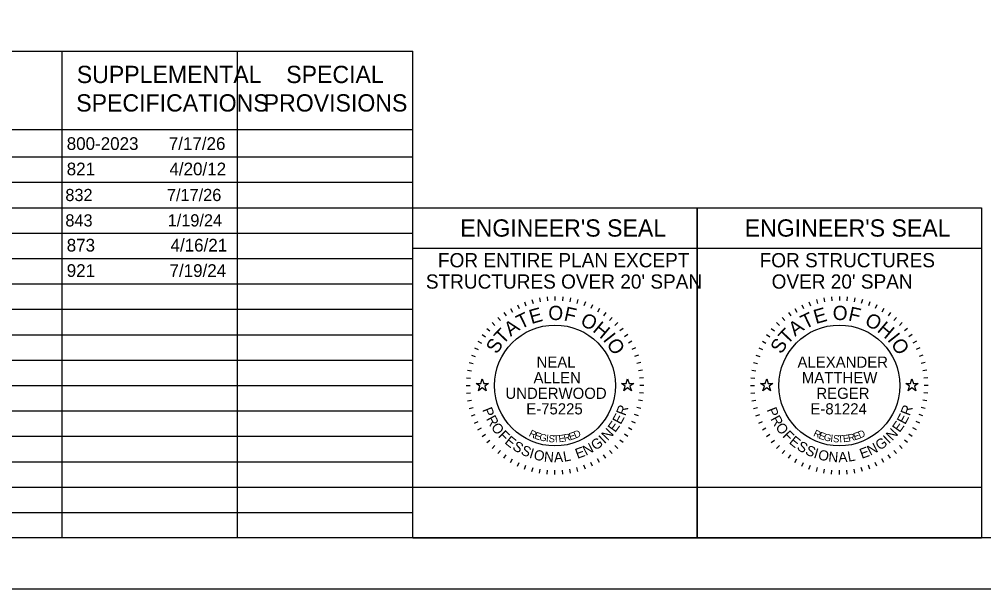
# Model space of a CAD drawing. Extents: x 0 to 34, y 0 to 22.
# Drawn here: x 19.73 to 29.22, y 0 to 5.6 of the extents above; entities that cross this region are included whole.
import ezdxf

# ---------------------------------------------------------------- set-up
doc = ezdxf.new("R2010")
doc.units = 0
for name, color, linetype in [('SH_Border', 7, 'Continuous'), ('SH_Cut_Line', 7, 'Continuous'), ('SH_Data', 7, 'Continuous'), ('SH_Seal', 7, 'Continuous'), ('SH_Text', 7, 'Continuous')]:
    doc.layers.add(name, color=color, linetype=linetype)

msp = doc.modelspace()

# ---------------------------------------------------------------- linework, layer by layer
at = {"layer": 'SH_Border'}
msp.add_lwpolyline([(1.5, 21.5), (33.5, 21.5), (33.5, 0.5), (1.5, 0.5)], close=True, dxfattribs=at)
at = {"layer": 'SH_Cut_Line'}
msp.add_lwpolyline([(0, 0), (34, 0), (34, 22), (0, 22)], close=True, dxfattribs=at)
at = {"layer": 'SH_Data'}
for p, q in [((10.15, 5.2917), (23.6, 5.2917)), ((20.15, 0.5), (20.15, 5.2917)), ((21.875, 0.5), (21.875, 5.2917)), ((23.6, 0.5), (23.6, 5.2917)), ((10.15, 4.5209), (23.6, 4.5209)), ((10.15, 4.25), (23.6, 4.25)), ((10.15, 4), (23.6, 4)), ((10.15, 3.75), (23.6, 3.75)), ((23.6, 0.5), (23.6, 3.75)), ((23.6, 3.75), (26.4, 3.75)), ((23.6, 0.5), (23.6, 3.75)), ((23.6, 3.75), (26.4, 3.75)), ((26.4, 3.75), (26.4, 0.5)), ((26.4, 0.5), (26.4, 3.75)), ((26.4, 0.5), (26.4, 3.75)), ((26.4, 3.75), (29.2, 3.75)), ((26.4, 3.75), (26.4, 0.5)), ((29.2, 3.75), (29.2, 0.5)), ((10.15, 3.5), (23.6, 3.5)), ((23.6, 3.35), (26.4, 3.35)), ((26.4, 3.35), (29.2, 3.35)), ((10.15, 3.25), (23.6, 3.25)), ((10.15, 3), (23.6, 3)), ((10.15, 2.75), (23.6, 2.75)), ((10.15, 2.5), (23.6, 2.5)), ((10.15, 2.25), (23.6, 2.25)), ((10.15, 2), (23.6, 2)), ((10.15, 1.75), (23.6, 1.75)), ((10.15, 1.5), (23.6, 1.5)), ((10.15, 1.25), (23.6, 1.25)), ((10.15, 1), (23.6, 1)), ((10.15, 0.75), (23.6, 0.75)), ((23.6, 0.5), (26.4, 0.5)), ((23.6, 0.5), (26.4, 0.5)), ((26.4, 0.5), (29.2, 0.5)), ((26.4, 0.5), (29.2, 0.5))]:
    msp.add_line(p, q, dxfattribs=at)
for points in [[(23.6, 0.5), (23.6, 1), (26.4, 1), (26.4, 0.5)], [(26.4, 0.5), (26.4, 1), (29.2, 1), (29.2, 0.5)]]:
    msp.add_lwpolyline(points, close=True, dxfattribs=at)
at = {"layer": 'SH_Seal'}
for p, q in [((24.8481, 2.8617), (24.855, 2.8223)), ((24.9237, 2.8717), (24.9272, 2.8318)), ((25, 2.875), (25, 2.835)), ((25.0763, 2.8717), (25.0728, 2.8318)), ((25.1519, 2.8617), (25.145, 2.8223)), ((27.6481, 2.8617), (27.655, 2.8223)), ((27.7237, 2.8717), (27.7272, 2.8318)), ((27.8, 2.875), (27.8, 2.835)), ((27.8763, 2.8717), (27.8728, 2.8318)), ((27.9519, 2.8617), (27.945, 2.8223)), ((24.5625, 2.7578), (24.5825, 2.7231)), ((24.6302, 2.793), (24.6471, 2.7568)), ((24.7007, 2.8222), (24.7144, 2.7846)), ((24.7735, 2.8452), (24.7839, 2.8065)), ((25.2265, 2.8452), (25.2161, 2.8065)), ((25.2993, 2.8222), (25.2856, 2.7846)), ((25.3698, 2.793), (25.3529, 2.7568)), ((25.4375, 2.7578), (25.4175, 2.7231)), ((27.3625, 2.7578), (27.3825, 2.7231)), ((27.4302, 2.793), (27.4471, 2.7568)), ((27.5007, 2.8222), (27.5144, 2.7846)), ((27.5735, 2.8452), (27.5839, 2.8065)), ((28.0265, 2.8452), (28.0161, 2.8065)), ((28.0993, 2.8222), (28.0856, 2.7846)), ((28.1698, 2.793), (28.1529, 2.7568)), ((28.2375, 2.7578), (28.2175, 2.7231)), ((24.4376, 2.6703), (24.4633, 2.6396)), ((24.4981, 2.7168), (24.5211, 2.684)), ((25.5019, 2.7168), (25.4789, 2.684)), ((25.5624, 2.6703), (25.5367, 2.6396)), ((27.2376, 2.6703), (27.2633, 2.6396)), ((27.2981, 2.7168), (27.3211, 2.684)), ((28.3019, 2.7168), (28.2789, 2.684)), ((28.3624, 2.6703), (28.3367, 2.6396)), ((24.3813, 2.6187), (24.4096, 2.5904)), ((25.6187, 2.6187), (25.5904, 2.5904)), ((27.1813, 2.6187), (27.2096, 2.5904)), ((28.4187, 2.6187), (28.3904, 2.5904)), ((24.2832, 2.5019), (24.316, 2.4789)), ((24.3297, 2.5624), (24.3604, 2.5367)), ((25.6703, 2.5624), (25.6396, 2.5367)), ((25.7168, 2.5019), (25.684, 2.4789)), ((27.0832, 2.5019), (27.116, 2.4789)), ((27.1297, 2.5624), (27.1604, 2.5367)), ((28.4703, 2.5624), (28.4396, 2.5367)), ((28.5168, 2.5019), (28.484, 2.4789)), ((24.2422, 2.4375), (24.2769, 2.4175)), ((25.7578, 2.4375), (25.7231, 2.4175)), ((27.0422, 2.4375), (27.0769, 2.4175)), ((28.5578, 2.4375), (28.5231, 2.4175)), ((24.1778, 2.2993), (24.2154, 2.2856)), ((24.207, 2.3698), (24.2432, 2.3529)), ((25.793, 2.3698), (25.7568, 2.3529)), ((25.8222, 2.2993), (25.7846, 2.2856)), ((26.9778, 2.2993), (27.0154, 2.2856)), ((27.007, 2.3698), (27.0432, 2.3529)), ((28.593, 2.3698), (28.5568, 2.3529)), ((28.6222, 2.2993), (28.5846, 2.2856)), ((24.1548, 2.2265), (24.1935, 2.2161)), ((25.8452, 2.2265), (25.8065, 2.2161)), ((26.9548, 2.2265), (26.9935, 2.2161)), ((28.6452, 2.2265), (28.6065, 2.2161)), ((24.1383, 2.1519), (24.1777, 2.145)), ((25.8617, 2.1519), (25.8223, 2.145)), ((26.9383, 2.1519), (26.9777, 2.145)), ((28.6617, 2.1519), (28.6223, 2.145)), ((24.125, 2), (24.165, 2)), ((24.1283, 2.0763), (24.1682, 2.0728)), ((25.8717, 2.0763), (25.8318, 2.0728)), ((25.875, 2), (25.835, 2)), ((26.925, 2), (26.965, 2)), ((26.9283, 2.0763), (26.9682, 2.0728)), ((28.6717, 2.0763), (28.6318, 2.0728)), ((28.675, 2), (28.635, 2)), ((24.1283, 1.9237), (24.1682, 1.9272)), ((25.8717, 1.9237), (25.8318, 1.9272)), ((26.9283, 1.9237), (26.9682, 1.9272)), ((28.6717, 1.9237), (28.6318, 1.9272)), ((24.1383, 1.8481), (24.1777, 1.855)), ((25.8617, 1.8481), (25.8223, 1.855)), ((26.9383, 1.8481), (26.9777, 1.855)), ((28.6617, 1.8481), (28.6223, 1.855)), ((24.1548, 1.7735), (24.1935, 1.7839)), ((24.1778, 1.7007), (24.2154, 1.7144)), ((25.8222, 1.7007), (25.7846, 1.7144)), ((25.8452, 1.7735), (25.8065, 1.7839)), ((26.9548, 1.7735), (26.9935, 1.7839)), ((26.9778, 1.7007), (27.0154, 1.7144)), ((28.6222, 1.7007), (28.5846, 1.7144)), ((28.6452, 1.7735), (28.6065, 1.7839)), ((24.207, 1.6302), (24.2432, 1.6471)), ((25.793, 1.6302), (25.7568, 1.6471)), ((27.007, 1.6302), (27.0432, 1.6471)), ((28.593, 1.6302), (28.5568, 1.6471)), ((24.2422, 1.5625), (24.2769, 1.5825)), ((24.2832, 1.4981), (24.316, 1.5211)), ((25.7168, 1.4981), (25.684, 1.5211)), ((25.7578, 1.5625), (25.7231, 1.5825)), ((27.0422, 1.5625), (27.0769, 1.5825)), ((27.0832, 1.4981), (27.116, 1.5211)), ((28.5168, 1.4981), (28.484, 1.5211)), ((28.5578, 1.5625), (28.5231, 1.5825)), ((24.3297, 1.4376), (24.3604, 1.4633)), ((25.6703, 1.4376), (25.6396, 1.4633)), ((27.1297, 1.4376), (27.1604, 1.4633)), ((28.4703, 1.4376), (28.4396, 1.4633)), ((24.3813, 1.3813), (24.4096, 1.4096)), ((24.4376, 1.3297), (24.4633, 1.3604)), ((25.5624, 1.3297), (25.5367, 1.3604)), ((25.6187, 1.3813), (25.5904, 1.4096)), ((27.1813, 1.3813), (27.2096, 1.4096)), ((27.2376, 1.3297), (27.2633, 1.3604)), ((28.3624, 1.3297), (28.3367, 1.3604)), ((28.4187, 1.3813), (28.3904, 1.4096)), ((24.4981, 1.2832), (24.5211, 1.316)), ((24.5625, 1.2422), (24.5825, 1.2769)), ((24.6302, 1.207), (24.6471, 1.2432)), ((25.3698, 1.207), (25.3529, 1.2432)), ((25.4375, 1.2422), (25.4175, 1.2769)), ((25.5019, 1.2832), (25.4789, 1.316)), ((27.2981, 1.2832), (27.3211, 1.316)), ((27.3625, 1.2422), (27.3825, 1.2769)), ((27.4302, 1.207), (27.4471, 1.2432)), ((28.1698, 1.207), (28.1529, 1.2432)), ((28.2375, 1.2422), (28.2175, 1.2769)), ((28.3019, 1.2832), (28.2789, 1.316)), ((24.7007, 1.1778), (24.7144, 1.2154)), ((24.7735, 1.1548), (24.7839, 1.1935)), ((24.8481, 1.1383), (24.855, 1.1777)), ((24.9237, 1.1283), (24.9272, 1.1682)), ((25, 1.125), (25, 1.165)), ((25.0763, 1.1283), (25.0728, 1.1682)), ((25.1519, 1.1383), (25.145, 1.1777)), ((25.2265, 1.1548), (25.2161, 1.1935)), ((25.2993, 1.1778), (25.2856, 1.2154)), ((27.5007, 1.1778), (27.5144, 1.2154)), ((27.5735, 1.1548), (27.5839, 1.1935)), ((27.6481, 1.1383), (27.655, 1.1777)), ((27.7237, 1.1283), (27.7272, 1.1682)), ((27.8, 1.125), (27.8, 1.165)), ((27.8763, 1.1283), (27.8728, 1.1682)), ((27.9519, 1.1383), (27.945, 1.1777)), ((28.0265, 1.1548), (28.0161, 1.1935)), ((28.0993, 1.1778), (28.0856, 1.2154))]:
    msp.add_line(p, q, dxfattribs=at)
for points in [[(24.2236, 2.02), (24.2705, 2.02), (24.285, 2.0645), (24.2995, 2.02), (24.3464, 2.02), (24.3085, 1.9924), (24.323, 1.9478), (24.285, 1.9754), (24.247, 1.9478), (24.2615, 1.9924)], [(25.6536, 2.02), (25.7005, 2.02), (25.715, 2.0645), (25.7295, 2.02), (25.7764, 2.02), (25.7385, 1.9924), (25.753, 1.9478), (25.715, 1.9754), (25.677, 1.9478), (25.6915, 1.9924)], [(27.0236, 2.02), (27.0705, 2.02), (27.085, 2.0645), (27.0995, 2.02), (27.1464, 2.02), (27.1085, 1.9924), (27.123, 1.9478), (27.085, 1.9754), (27.047, 1.9478), (27.0615, 1.9924)], [(28.4536, 2.02), (28.5005, 2.02), (28.515, 2.0645), (28.5295, 2.02), (28.5764, 2.02), (28.5385, 1.9924), (28.553, 1.9478), (28.515, 1.9754), (28.477, 1.9478), (28.4915, 1.9924)]]:
    msp.add_lwpolyline(points, close=True, dxfattribs=at)
for centre in [(25, 2), (27.8, 2)]:
    msp.add_circle(centre, 0.595, dxfattribs=at)

# ---------------------------------------------------------------- texts
at = {"layer": 'SH_Data'}
for s, height, p in [("ENGINEER'S SEAL", 0.17, (24.0676, 3.465)), ("ENGINEER'S SEAL", 0.17, (26.8676, 3.465)), ('FOR ENTIRE PLAN EXCEPT', 0.14, (23.8479, 3.1631)), ('FOR STRUCTURES', 0.14, (27.0148, 3.1631)), ("STRUCTURES OVER 20' SPAN", 0.14, (23.7291, 2.9531)), ("OVER 20' SPAN", 0.14, (27.1329, 2.9531))]:
    msp.add_text(s, height=height, dxfattribs=at).set_placement(p)
at = {"layer": 'SH_Seal'}
for s, height, rotation, p in [('E', 0.14, 15.75706, (24.7684, 2.6038)), ('O', 0.14, 359.78119, (24.9347, 2.6443)), ('F', 0.14, 347.43619, (25.0811, 2.6417)), ('E', 0.14, 15.75706, (27.5684, 2.6038)), ('O', 0.14, 359.78119, (27.7347, 2.6443)), ('F', 0.14, 347.43619, (27.8811, 2.6417)), ('T', 0.14, 25.71674, (24.6616, 2.5518)), ('O', 0.14, 332.25863, (25.2398, 2.6015)), ('T', 0.14, 25.71674, (27.4616, 2.5518)), ('O', 0.14, 332.25863, (28.0398, 2.6015)), ('T', 0.14, 46.4344, (24.4883, 2.3964)), ('A', 0.14, 36.47472, (24.5634, 2.4781)), ('H', 0.14, 319.91363, (25.3632, 2.5361)), ('T', 0.14, 46.4344, (27.2883, 2.3964)), ('A', 0.14, 36.47472, (27.3634, 2.4781)), ('H', 0.14, 319.91363, (28.1632, 2.5361)), ('I', 0.14, 308.36695, (25.4665, 2.4483)), ('I', 0.14, 308.36695, (28.2665, 2.4483)), ('S', 0.14, 57.19238, (24.4281, 2.3014)), ('O', 0.14, 303.14906, (25.5021, 2.4089)), ('S', 0.14, 57.19238, (27.2281, 2.3014)), ('O', 0.14, 303.14906, (28.3021, 2.4089)), ('R', 0.1, 69.23216, (25.6919, 1.6954)), ('R', 0.1, 69.23216, (28.4919, 1.6954)), ('P', 0.1, 291.49398, (24.2823, 1.7621)), ('R', 0.1, 298.73106, (24.319, 1.6717)), ('E', 0.1, 61.99508, (25.6476, 1.6098)), ('P', 0.1, 291.49398, (27.0823, 1.7621)), ('R', 0.1, 298.73106, (27.119, 1.6717)), ('E', 0.1, 61.99508, (28.4476, 1.6098)), ('O', 0.1, 306.46664, (24.3655, 1.5883)), ('E', 0.1, 54.75801, (25.5933, 1.5314)), ('O', 0.1, 306.46664, (27.1655, 1.5883)), ('E', 0.1, 54.75801, (28.3933, 1.5314)), ('F', 0.1, 314.7068, (24.4343, 1.4983)), ('R', 0.07, 334.48695, (24.7375, 1.5051)), ('E', 0.07, 341.03996, (24.7906, 1.4801)), ('G', 0.07, 347.47515, (24.8414, 1.4618)), ('R', 0.07, 11.91844, (25.0925, 1.4474)), ('E', 0.07, 17.68363, (25.1498, 1.4602)), ('D', 0.07, 23.30524, (25.201, 1.477)), ('N', 0.1, 47.02243, (25.5202, 1.4508)), ('F', 0.1, 314.7068, (27.2343, 1.4983)), ('R', 0.07, 334.48695, (27.5375, 1.5051)), ('E', 0.07, 341.03996, (27.5906, 1.4801)), ('G', 0.07, 347.47515, (27.6414, 1.4618)), ('R', 0.07, 11.91844, (27.8925, 1.4474)), ('E', 0.07, 17.68363, (27.9498, 1.4602)), ('D', 0.07, 23.30524, (28.001, 1.477)), ('N', 0.1, 47.02243, (28.3202, 1.4508)), ('E', 0.1, 321.43929, (24.4978, 1.4348)), ('S', 0.1, 328.67637, (24.5743, 1.3752)), ('I', 0.07, 353.78581, (24.9091, 1.4468)), ('S', 0.07, 356.89262, (24.9358, 1.4429)), ('T', 0.07, 3.00609, (24.9857, 1.4387)), ('E', 0.07, 6.01169, (25.0389, 1.4412)), ('N', 0.1, 27.31129, (25.3045, 1.3075)), ('G', 0.1, 35.04687, (25.3981, 1.357)), ('I', 0.1, 43.28703, (25.4868, 1.4214)), ('E', 0.1, 321.43929, (27.2978, 1.4348)), ('S', 0.1, 328.67637, (27.3743, 1.3752)), ('I', 0.07, 353.78581, (27.7091, 1.4468)), ('S', 0.07, 356.89262, (27.7358, 1.4429)), ('T', 0.07, 3.00609, (27.7857, 1.4387)), ('E', 0.07, 6.01169, (27.8389, 1.4412)), ('N', 0.1, 27.31129, (28.1045, 1.3075)), ('G', 0.1, 35.04687, (28.1981, 1.357)), ('I', 0.1, 43.28703, (28.2868, 1.4214)), ('S', 0.1, 335.91345, (24.6564, 1.3266)), ('I', 0.1, 343.15053, (24.7406, 1.2897)), ('O', 0.1, 346.88592, (24.7839, 1.2751)), ('N', 0.1, 355.12608, (24.8888, 1.2517)), ('A', 0.1, 2.86166, (24.9923, 1.2437)), ('L', 0.1, 10.09874, (25.0894, 1.249)), ('E', 0.1, 20.07421, (25.2212, 1.277)), ('S', 0.1, 335.91345, (27.4564, 1.3266)), ('I', 0.1, 343.15053, (27.5406, 1.2897)), ('O', 0.1, 346.88592, (27.5839, 1.2751)), ('N', 0.1, 355.12608, (27.6888, 1.2517)), ('A', 0.1, 2.86166, (27.7923, 1.2437)), ('L', 0.1, 10.09874, (27.8894, 1.249)), ('E', 0.1, 20.07421, (28.0212, 1.277))]:
    msp.add_text(s, height=height, rotation=rotation, dxfattribs=at).set_placement(p)
for s, p in [('NEAL', (24.8188, 2.1749)), ('ALEXANDER', (27.3877, 2.1749)), ('ALLEN', (24.7889, 2.0216)), ('MATTHEW', (27.4304, 2.0216)), ('UNDERWOOD', (24.5122, 1.8684)), ('REGER', (27.5733, 1.8684)), ('E-75225', (24.7173, 1.7151)), ('E-81224', (27.5145, 1.7151))]:
    msp.add_text(s, height=0.11, dxfattribs=at).set_placement(p)
at = {"layer": 'SH_Text'}
for s, height, p in [('SUPPLEMENTAL', 0.17, (20.2925, 4.9763)), ('SPECIAL', 0.17, (22.3542, 4.9763)), ('SPECIFICATIONS', 0.17, (20.2871, 4.6963)), ('PROVISIONS', 0.17, (22.1323, 4.6963)), ('800-2023', 0.125, (20.1933, 4.3184)), ('7/17/26', 0.125, (21.1983, 4.3184)), ('821', 0.125, (20.1933, 4.0684)), ('4/20/12', 0.125, (21.2047, 4.0684)), ('832', 0.12, (20.18, 3.815)), ('7/17/26', 0.12, (21.1799, 3.815)), ('843', 0.12, (20.18, 3.565)), ('1/19/24', 0.12, (21.1873, 3.565)), ('873', 0.125, (20.1933, 3.3184)), ('4/16/21', 0.125, (21.2153, 3.3184)), ('921', 0.125, (20.1933, 3.0684)), ('7/19/24', 0.125, (21.2054, 3.0684))]:
    msp.add_text(s, height=height, dxfattribs=at).set_placement(p)

doc.saveas('drawing.dxf')
